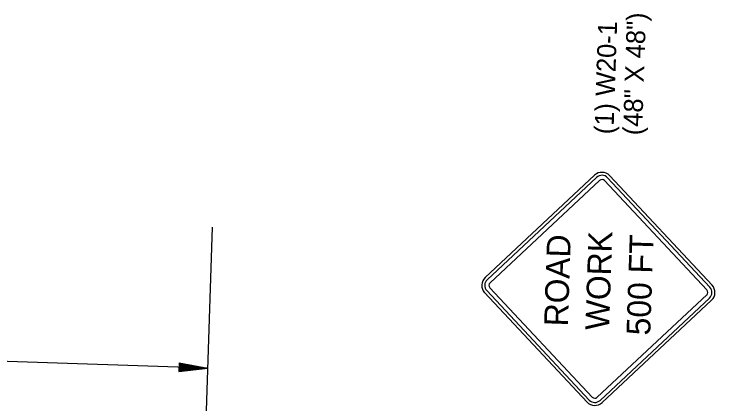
# Model space of a CAD drawing. Extents: x 977269 to 979191, y 1525946 to 1526973.
# Drawn here: x 978195.4 to 978416.4, y 1526723.4 to 1526846.4 of the extents above; entities that cross this region are included whole.
import ezdxf

# ---------------------------------------------------------------- set-up
doc = ezdxf.new("R2010")
doc.units = 0
for name, color, linetype in [('R_Border', 7, 'Continuous'), ('STAMP', 7, 'Continuous'), ('STAMP_PP', 7, 'Continuous')]:
    doc.layers.add(name, color=color, linetype=linetype)

msp = doc.modelspace()

# ---------------------------------------------------------------- linework, layer by layer
at = {"layer": 'STAMP'}
for p, q in [((978255.36, 1526699.62), (978258.01, 1526779.11)), ((978256.53, 1526734.66), (977948.57, 1526744.93)), ((978247.51, 1526736.32), (978247.42, 1526733.6)), ((978247.5, 1526736.1), (978255.02, 1526734.71)), ((978247.5, 1526735.87), (978253.46, 1526734.76)), ((978247.51, 1526736.32), (978256.53, 1526734.66)), ((978247.42, 1526733.6), (978256.53, 1526734.66)), ((978247.43, 1526733.83), (978255.02, 1526734.71)), ((978247.44, 1526734.29), (978251.95, 1526734.81)), ((978247.44, 1526734.06), (978253.46, 1526734.76)), ((978247.45, 1526734.52), (978250.41, 1526734.87)), ((978247.46, 1526734.75), (978248.9, 1526734.92)), ((978247.47, 1526735.18), (978248.9, 1526734.92)), ((978247.48, 1526735.4), (978250.41, 1526734.87)), ((978247.49, 1526735.64), (978251.95, 1526734.81))]:
    msp.add_line(p, q, dxfattribs=at)
at = {"layer": 'STAMP_PP'}
for p, q in [((978343.97, 1526763.27), (978378.48, 1526795.55)), ((978344.62, 1526762.58), (978379.12, 1526794.86)), ((978345.51, 1526761.63), (978380.02, 1526793.91)), ((978381.61, 1526793.85), (978413.89, 1526759.35)), ((978382.57, 1526794.75), (978414.84, 1526760.24)), ((978383.25, 1526795.39), (978415.53, 1526760.88)), ((978376.09, 1526723.99), (978343.82, 1526758.5)), ((978376.78, 1526724.63), (978344.5, 1526759.14)), ((978377.74, 1526725.53), (978345.46, 1526760.04)), ((978413.83, 1526757.76), (978379.33, 1526725.48)), ((978414.73, 1526756.8), (978380.22, 1526724.52)), ((978415.37, 1526756.11), (978380.86, 1526723.83))]:
    msp.add_line(p, q, dxfattribs=at)
for centre, radius, start, end in [((978380.79, 1526793.08), 3.37, 43.0901, 133.0901), ((978380.79, 1526793.08), 2.44, 43.0901, 133.0901), ((978380.79, 1526793.08), 1.12, 43.0901, 133.0901), ((978346.28, 1526760.8), 3.38, 133.0901, 223.0901), ((978346.28, 1526760.8), 2.44, 133.0901, 223.0901), ((978346.28, 1526760.8), 1.13, 133.0901, 223.0901), ((978413.06, 1526758.58), 2.44, 313.0901, 43.0901), ((978413.06, 1526758.58), 3.38, 313.0901, 43.0901), ((978413.06, 1526758.58), 1.13, 313.0901, 43.0901), ((978378.56, 1526726.3), 1.12, 223.0901, 313.0901), ((978378.56, 1526726.3), 3.38, 223.0901, 313.0901), ((978378.56, 1526726.3), 2.44, 223.0901, 313.0901)]:
    msp.add_arc(centre, radius, start, end, dxfattribs=at)

# ---------------------------------------------------------------- texts
at = {"layer": 'R_Border'}
for s, p in [('(48" X 48")', (978393.42, 1526808.09)), ('(1) W20-1', (978384.42, 1526808.39))]:
    msp.add_text(s, height=6, rotation=88.0901, dxfattribs=at).set_placement(p)
at = {"layer": 'STAMP_PP'}
for s, p in [(' ROAD ', (978369.96, 1526744.99)), ('WORK', (978383.05, 1526746.58)), ('500 FT ', (978396.02, 1526744.93))]:
    msp.add_text(s, height=7.5, rotation=88.0901, dxfattribs=at).set_placement(p)

doc.saveas('drawing.dxf')
